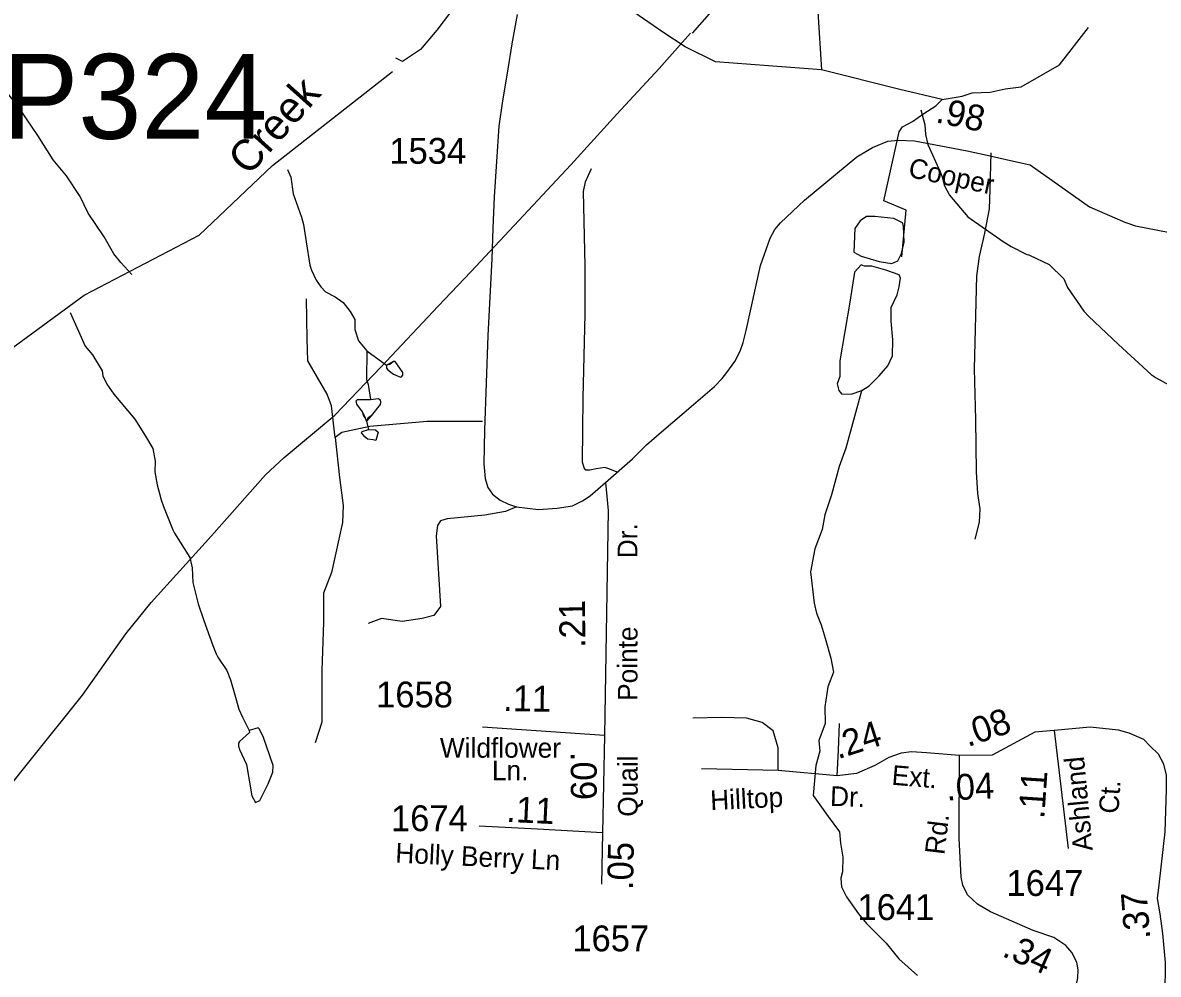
# Model space of a CAD drawing. Extents: x 1473865 to 1648260, y 639067 to 773536.
# Drawn here: x 1520569 to 1526062, y 681743 to 686345 of the extents above; entities that cross this region are included whole.
import ezdxf

# ---------------------------------------------------------------- set-up
doc = ezdxf.new("R2010")
doc.units = 0
for name, color, linetype in [('Exist Hydrographic Creek Single Shore', 7, 'Continuous'), ('Exist Hydrographic Creek Single Shore Label', 7, 'Continuous'), ('Exist Hydrographic Misc Water Feature', 7, 'Continuous'), ('Exist Hydrographic Pond Over 1500 Sq Ft', 7, 'Continuous'), ('Exist Hydrographic Pond Under 1500 Sq Ft', 7, 'Continuous'), ('Exist Road Non-System Type 51', 7, 'Continuous'), ('Exist Road Secondary Mileage Hundredths English Label', 7, 'Continuous'), ('Exist Road Secondary Structure Pipe Number Label', 7, 'Continuous'), ('Exist Road Secondary Type 51 Attributed', 7, 'Continuous'), ('Exist Road Secondary Type 51 Label', 7, 'Continuous'), ('Exist Road Secondary Type 51 Number Label', 7, 'Continuous'), ('Exist Utilities Electrical Transmission Line', 7, 'Continuous')]:
    doc.layers.add(name, color=color, linetype=linetype)

msp = doc.modelspace()

# ---------------------------------------------------------------- linework, layer by layer
at = {"layer": 'Exist Hydrographic Creek Single Shore'}
for points in [[(1523666, 686298.8), (1523432.2, 686461.6), (1523382.8, 686513), (1523294.5, 686557.7), (1523201.6, 686564.8), (1522986.7, 686628.2), (1522734, 686471.2), (1522659.1, 686431.8), (1522639.1, 686396.5), (1522572, 686309.4), (1522493.2, 686215.3), (1522406.1, 686157.7), (1522373.2, 686173.5)], [(1525016, 685972.9), (1525113.7, 685989.4), (1525161.9, 686005.9), (1525249, 686009.4), (1525320.8, 686024.7), (1525398.4, 686035.3), (1525584.4, 686140.6), (1525724.7, 686321.8)], [(1525016, 685972.9), (1524812.4, 686022.3), (1524432.3, 686116.3), (1523920.5, 686155.3), (1523773.5, 686227.8), (1523666, 686298.8)], [(1517072, 680044.5), (1517310.1, 680437), (1517438.1, 680611.7), (1517759.1, 680897.3), (1518003.1, 681043.4), (1518182.1, 681266.3), (1518591.3, 682427), (1519143.1, 682993.2), (1519774.2, 683899.6), (1519995.1, 684206.9), (1520521.2, 684774.1), (1520867.2, 685026.4), (1521422.2, 685317.2), (1521777.2, 685654.6), (1522357.9, 686108.2)], [(1524630.1, 684570), (1524623.9, 684558.7), (1524550, 684287.9), (1524518.3, 684198.5), (1524480.6, 684062), (1524449, 683964.4), (1524435.9, 683894.1), (1524400.6, 683800.8), (1524379.7, 683689.3), (1524397.5, 683537.1), (1524408.8, 683488.4), (1524431.8, 683432.2), (1524450.8, 683367.8), (1524477.5, 683271.2), (1524490.2, 683203.7)], [(1524490.2, 683203.7), (1524463, 683132.4), (1524449.5, 683035.5), (1524450.3, 682955.1), (1524420.6, 682873.5), (1524424.1, 682821.8), (1524405.3, 682752.3), (1524392.4, 682607.6), (1524465.3, 682505.2), (1524519.4, 682432.3), (1524525.2, 682376.6), (1524536.2, 682309.9), (1524535.2, 682238.5), (1524526.6, 682208.3), (1524529.9, 682166.5), (1524553.2, 682117.5), (1524611.9, 682035.1), (1524651.1, 681988.4), (1524745.9, 681892.9), (1524806.7, 681817.8), (1524897.3, 681736.4)]]:
    msp.add_lwpolyline(points, dxfattribs=at)
at = {"layer": 'Exist Hydrographic Misc Water Feature'}
for p, q in [((1522233.7, 684757.5), (1522328.7, 684688.3)), ((1522232.3, 684417), (1522241.9, 684377.4))]:
    msp.add_line(p, q, dxfattribs=at)
for points in [[(1524415.1, 686396.7), (1524432.3, 686116.3)], [(1521097.3, 685127.6), (1521044.1, 685184.5), (1521010.6, 685227), (1520963.9, 685310), (1520885.8, 685423.2), (1520847, 685503.6), (1520780.5, 685605), (1520715.8, 685681.8), (1520641.6, 685799), (1520549.6, 685934.6), (1520486.8, 686015.5), (1520398.1, 686096.9), (1520323.1, 686159.9), (1520251.9, 686221.3), (1520207.1, 686290.3), (1520168.2, 686352.6)], [(1524734.3, 685483.4), (1524808.9, 685816.4), (1524825.4, 685841.1), (1524872.4, 685867), (1524927.7, 685905.8), (1524986.6, 685942.3), (1525016, 685972.9)], [(1524913.4, 685923.7), (1524932.3, 685851.1), (1524935.3, 685803.5), (1524946.7, 685755.6), (1525006.6, 685623.9), (1525016.2, 685599.9), (1525027.6, 685556.2), (1525052.7, 685511.4), (1525141.3, 685406.2), (1525311.4, 685287.1), (1525351, 685262.5), (1525422.4, 685225.8), (1525438.5, 685221.3), (1525533.9, 685175.9), (1525604.6, 685106.4), (1525622.1, 685064.2), (1525702.2, 684949.3), (1525723.9, 684925.1), (1525869.9, 684788.3), (1526027.5, 684644), (1526051.2, 684627.1), (1526116.8, 684592.2)], [(1521849.5, 685634.3), (1521866.8, 685597.8), (1521877.5, 685517.2), (1521917.9, 685404.8), (1521927.2, 685368.5), (1521939.9, 685284.6), (1521958.2, 685171.7), (1521965.9, 685147.8), (1521989.1, 685099.7), (1522010.6, 685067.3), (1522034.4, 685043), (1522079.8, 685018.3), (1522119.5, 684991.2), (1522152.9, 684948.7), (1522176.3, 684908.9), (1522175.4, 684860.5), (1522192.7, 684805.9), (1522233.7, 684757.5)], [(1520798.1, 684944), (1520871.5, 684780.9), (1520907, 684738.4), (1520953.6, 684661.9), (1520957.5, 684637.2), (1520976.8, 684597.4), (1521010, 684548.3), (1521112.2, 684427.3), (1521162.9, 684345.8), (1521198, 684285.3), (1521209.1, 684225.1), (1521208.2, 684173.4), (1521219.3, 684109.2), (1521238.1, 684036.6), (1521249.5, 684004.3), (1521295.7, 683891.8), (1521303.6, 683876.1), (1521377.8, 683758.9), (1521388.9, 683708.6), (1521391.9, 683638), (1521418.2, 683534), (1521445, 683453), (1521489.1, 683332.3), (1521504.4, 683292.6), (1521512.2, 683276.1), (1521557.1, 683211.2), (1521574.4, 683167.3), (1521595.3, 683094.7), (1521614.2, 683024.5), (1521631.7, 682986.5), (1521664.6, 682921.8)], [(1522233.7, 684757.5), (1522231.7, 684619.7), (1522239.3, 684595.8), (1522252.1, 684523.3)], [(1522328.7, 684688.3), (1522328.4, 684674.4), (1522334.5, 684666), (1522362.1, 684645.8), (1522395.9, 684631.2), (1522401.9, 684632.7), (1522408, 684640.8), (1522408.3, 684653.1), (1522371.2, 684707.1), (1522363.2, 684705.7), (1522344.8, 684692.1), (1522328.7, 684688.3)], [(1522328.7, 684688.3), (1522328.4, 684674.4), (1522334.5, 684666), (1522362.1, 684645.8), (1522395.9, 684631.2), (1522401.9, 684632.7), (1522408, 684640.8), (1522408.3, 684653.1), (1522371.2, 684707.1), (1522363.2, 684705.7), (1522328.7, 684688.3)], [(1522232.3, 684417), (1522226.7, 684431.9), (1522218.9, 684441.9), (1522213.2, 684463.3), (1522185.8, 684500), (1522182.1, 684516.5), (1522188.1, 684522.1), (1522252.1, 684523.3)], [(1522232.3, 684417), (1522226.7, 684431.9), (1522213.2, 684463.3), (1522185.8, 684500), (1522182.1, 684516.5), (1522188.1, 684522.1), (1522252.1, 684523.3)], [(1522252.1, 684523.3), (1522290.2, 684526.6), (1522298.1, 684520.7), (1522299.9, 684510), (1522297.8, 684498.6), (1522254.9, 684442.8), (1522238.6, 684431.7), (1522232.3, 684417)], [(1522252.1, 684523.3), (1522290.2, 684526.6), (1522298.1, 684520.7), (1522299.9, 684510), (1522297.8, 684498.6), (1522254.9, 684442.8), (1522232.3, 684417)], [(1522241.9, 684377.4), (1522275.8, 684375.1), (1522287.7, 684364.2), (1522277, 684325), (1522265, 684326.9), (1522237.1, 684331.5), (1522223.2, 684341.7), (1522207.6, 684361.7), (1522211.6, 684367.4), (1522241.9, 684377.4)], [(1521664.6, 682921.8), (1521666.5, 682911.9), (1521617.9, 682868.5), (1521613.6, 682860.4), (1521613.5, 682846.5), (1521617.1, 682830), (1521652.1, 682757.9), (1521677.6, 682605.6), (1521695.2, 682573.2), (1521715.3, 682582.7), (1521756.7, 682663.9), (1521779.6, 682720), (1521780, 682752), (1521764.8, 682800), (1521734.2, 682888.4), (1521714.9, 682929), (1521708.8, 682934.8), (1521664.6, 682921.8)]]:
    msp.add_lwpolyline(points, dxfattribs=at)
at = {"layer": 'Exist Hydrographic Pond Over 1500 Sq Ft'}
for points in [[(1524620.6, 685386.9), (1524594.7, 685349.3), (1524588.9, 685235.1), (1524624.2, 685216.3), (1524711.2, 685190.4), (1524772.4, 685181), (1524801.8, 685192.8), (1524819.5, 685229.3), (1524832.4, 685283.4), (1524828.9, 685361), (1524825.4, 685377.5), (1524783, 685397.5), (1524690.1, 685408.1), (1524651.2, 685406.9)], [(1524624.2, 685174), (1524592.4, 685138.7), (1524570, 684993.9), (1524521.8, 684709.2), (1524521.8, 684633.9), (1524508.8, 684598.6), (1524517.1, 684566.8), (1524530, 684550.3), (1524575.9, 684549.1), (1524627.7, 684565.6), (1524663, 684588), (1524711.2, 684636.2), (1524753.6, 684685.6), (1524776, 684733.9), (1524777.1, 684811.5), (1524770.1, 684902.1), (1524770.1, 684966.9), (1524798.3, 685028), (1524808.9, 685066.9), (1524814.8, 685109.2), (1524808.9, 685125.7), (1524744.2, 685148.1), (1524677.1, 685166.9), (1524640.6, 685166.9)]]:
    msp.add_lwpolyline(points, close=True, dxfattribs=at)
at = {"layer": 'Exist Hydrographic Pond Under 1500 Sq Ft'}
msp.add_lwpolyline([(1524821.2, 685212.5), (1524842.2, 685438.6), (1524734.3, 685483.4)], dxfattribs=at)
at = {"layer": 'Exist Road Non-System Type 51'}
for points in [[(1525176.3, 683846.3), (1525197.8, 683929.9), (1525201.1, 683993.6), (1525188.6, 684067.9), (1525182.5, 684172.1), (1525179.4, 684426.1), (1525172.1, 684670.2), (1525184.6, 685119.9), (1525196.5, 685213.7), (1525222.6, 685327.3), (1525245, 685444.9), (1525248.7, 685538.9), (1525253.7, 685714.8)], [(1523443.9, 684171.7), (1523409.8, 684185.7), (1523385, 684193.4), (1523343.1, 684187.2), (1523312, 684181), (1523293.4, 684181), (1523284.1, 684191.9), (1523276.4, 684219.8), (1523279.5, 684530.2), (1523289.6, 684934.6), (1523290.3, 685168.2), (1523281.8, 685529.1), (1523291.1, 685575.7), (1523319.8, 685640.1)], [(1522080.3, 684338.4), (1522062.5, 684491.9), (1522041.1, 684549), (1521948.4, 684709.6), (1521944.8, 684816.7), (1521941.2, 685009.4)], [(1522793.5, 684416.9), (1522526.1, 684416.9), (1522247.9, 684391.9), (1522112.4, 684363.4), (1522080.3, 684338.4)], [(1522080.3, 684338.4), (1522101.7, 684145.6), (1522119.5, 684010), (1522116, 683927.9), (1522062.5, 683685.2), (1522023.3, 683585.2), (1522023.3, 683446), (1522016.2, 683212.6), (1522016.2, 683034.2), (1522016.2, 682962.8), (1521984.1, 682862.8)], [(1522957.6, 684002.9), (1522904.1, 683981.4), (1522804.2, 683963.6), (1522622.4, 683945.7), (1522590.3, 683935), (1522576, 683913.6), (1522568.9, 683863.6), (1522590.3, 683521), (1522558.2, 683478.2), (1522501.1, 683463.9), (1522404.8, 683449.6), (1522305, 683463.9), (1522240.8, 683438.9)], [(1524222.8, 682727.9), (1524222.8, 682837.3), (1524198.3, 682920.3), (1524145.4, 682960), (1524070.5, 682980.6), (1523951.5, 682985), (1523810.4, 682982.1)], [(1524508.2, 682702.9), (1524515.7, 682827.2), (1524520.6, 682956.4)]]:
    msp.add_lwpolyline(points, dxfattribs=at)
at = {"layer": 'Exist Road Secondary Type 51 Attributed'}
msp.add_line((1525558.4, 682921.4), (1525625.9, 682350.7), dxfattribs=at)
for points in [[(1522961.5, 686384.8), (1522935.6, 686242.4), (1522913.3, 686110.6), (1522889.7, 685967), (1522872.1, 685844.7), (1522849.7, 685503.4), (1522843.8, 685351.6), (1522838, 685202.2), (1522819, 684831.8), (1522802.7, 684373.8), (1522799.1, 684211.4), (1522806.2, 684139.7), (1522819.1, 684097.3), (1522841.5, 684065.5), (1522879.1, 684035), (1522919.2, 684016.1), (1522957.6, 684002.9), (1523063.9, 683990.2), (1523154.5, 683997.3), (1523228.6, 684009), (1523276.9, 684032.6), (1523313.3, 684056.1), (1523387.5, 684120.8)], [(1523387.5, 684120.8), (1523519.3, 684236.1), (1523586.7, 684303.9), (1523659.3, 684365.6), (1523768.7, 684459.7), (1523914.6, 684585.6), (1523952.3, 684623.3), (1523974.6, 684652.9), (1524013.5, 684706.8), (1524039.4, 684756.2), (1524053.5, 684797.4), (1524068.8, 684856.2), (1524138.4, 685170.4), (1524184.1, 685303.4), (1524206.4, 685344.6), (1524234.7, 685377.5), (1524351.2, 685486.9), (1524604.2, 685696.4), (1524679.5, 685741.1), (1524753.6, 685771.7), (1524803, 685776.4), (1524883, 685774.1), (1525137.2, 685724.6), (1525233.7, 685704.6), (1525346.6, 685678.7), (1525441.7, 685657.7), (1525728.6, 685453.7), (1525900.2, 685380.7), (1525952.4, 685362.8), (1526333.1, 685287.5)], [(1523387.5, 684120.8), (1523401.6, 683985.5), (1523383.9, 682897.1)], [(1523383.9, 682897.1), (1522792.9, 682938.1)], [(1525558.4, 682921.4), (1525465.4, 682913), (1525258.4, 682803.1), (1525101, 682801.3)], [(1525953.8, 681077.9), (1526040.9, 681294.4), (1526079.7, 681429.8), (1526092.7, 681534.5), (1526095, 681645.1), (1526097.4, 681799.2), (1526083.2, 681939.3), (1526071.5, 682034.6), (1526058.5, 682108.7), (1526065.6, 682175.8), (1526095, 682432.3), (1526100.9, 682637), (1526100.9, 682706.5), (1526087.9, 682758.2), (1526062.1, 682807.7), (1526023.2, 682846.5), (1525991.5, 682878.3), (1525921.7, 682908.8), (1525870.2, 682922.6), (1525731.6, 682938.3), (1525558.4, 682921.4)], [(1523383.9, 682897.1), (1523373.6, 682426.9)], [(1525101, 682801.3), (1524940.5, 682814), (1524868.7, 682818.2), (1524818, 682811.9), (1524758.8, 682790.7), (1524691.2, 682752.7), (1524602.5, 682714.6), (1524508.2, 682702.9), (1524222.8, 682727.9), (1523852.7, 682735.8)], [(1525528.2, 681173.3), (1525620.5, 681502.2), (1525666.7, 681694.4), (1525672.6, 681726), (1525674.5, 681764.8), (1525667.9, 681801.6), (1525644.3, 681847.5), (1525614.9, 681881.6), (1525556.1, 681920.4), (1525455.9, 681954.8), (1525250.2, 682045.2), (1525186.6, 682081.6), (1525138.4, 682126.4), (1525117.2, 682173.4), (1525109, 682212.3), (1525099.5, 682400.5), (1525101, 682801.3)], [(1523373.6, 682426.9), (1523058.4, 682445.1), (1522777, 682458.3)], [(1523373.6, 682426.9), (1523368.9, 682177.9)]]:
    msp.add_lwpolyline(points, dxfattribs=at)
at = {"layer": 'Exist Utilities Electrical Transmission Line'}
for points in [[(1526240.6, 689003.8), (1526008, 688741.5), (1525759.2, 688463.6), (1525478, 688150.3), (1525196.9, 687845), (1524970.3, 687582.7), (1524686.9, 687265.4), (1524466.8, 687019.1), (1524226.2, 686747.1), (1524006.3, 686520.8), (1523806.5, 686293.9)], [(1520286.1, 682378.8), (1520605.1, 682776.9), (1520858.8, 683092.4), (1521067.9, 683388.5), (1521190.6, 683540.3), (1521482.2, 683863.2), (1521743.5, 684158.3), (1521833.1, 684242.7), (1522078.5, 684446.2), (1522302.7, 684680.2), (1522578, 684973.2), (1522736.8, 685140.3), (1522969.1, 685388.1), (1523219.9, 685657.6), (1523442.3, 685901.7), (1523648.1, 686123.8), (1523799.2, 686293.9)]]:
    msp.add_lwpolyline(points, dxfattribs=at)

# ---------------------------------------------------------------- texts
at = {"layer": 'Exist Hydrographic Creek Single Shore Label'}
msp.add_text('Creek', height=150, rotation=48.1908, dxfattribs=at).set_placement((1521661.8, 685599.5))
at = {"layer": 'Exist Road Secondary Mileage Hundredths English Label'}
for s, rotation, p in [('.98', 347.9733, (1524980.6, 685864.1)), ('.21', 90.803, (1523291.4, 683321.5)), ('.11', 359.0127, (1522892.2, 683016.2)), ('.08', 18.773, (1525140.2, 682841.2)), ('.24', 17.9873, (1524512.5, 682782)), ('.09', 270.094, (1523220.2, 682818.1)), ('.04', 2.8213, (1525038.8, 682582.6)), ('.11', 86.1339, (1525510.1, 682492.1)), ('.11', 357.3204, (1522906.5, 682480)), ('.05', 88.9299, (1523521.2, 682149.2)), ('.37', 94.5461, (1526023.4, 681914.7)), ('.34', 336.2487, (1525301.3, 681832.5))]:
    msp.add_text(s, height=125, rotation=rotation, dxfattribs=at).set_placement(p)
at = {"layer": 'Exist Road Secondary Structure Pipe Number Label'}
msp.add_text('P324', height=410.1, dxfattribs=at).set_placement((1520472.2, 685783.2))
at = {"layer": 'Exist Road Secondary Type 51 Label'}
for s, rotation, p in [('Cooper', 347.9733, (1524848, 685600)), ('Dr.', 90, (1523541.9, 683754.7)), ('Pointe', 90, (1523542.8, 683064.9)), ('Quail', 90, (1523543.7, 682504.5)), ('Ext.', 355.2485, (1524769.8, 682659.8)), ('Ashland', 95.3638, (1525744.9, 682342.7)), ('Hilltop', 2.8213, (1523896.9, 682536.1)), ('Dr.', 357.888, (1524472.9, 682557.6)), ('Ct.', 86.1339, (1525868.9, 682517.2)), ('Rd.', 83.1127, (1525026.8, 682317.8)), ('Holly Berry Ln', 357.3204, (1522370, 682283.1))]:
    msp.add_text(s, height=95, rotation=rotation, dxfattribs=at).set_placement(p)
for s, p in [('Wildflower', (1522587.1, 682790.2)), ('Ln.', (1522838.8, 682681.4))]:
    msp.add_text(s, height=95, dxfattribs=at).set_placement(p)
at = {"layer": 'Exist Road Secondary Type 51 Number Label'}
for s, p in [('1534', (1522342.5, 685662.4)), ('1658', (1522278.5, 683033.5)), ('1674', (1522350.3, 682434.9)), ('1647', (1525327.4, 682121.6)), ('1641', (1524606.9, 682005.1)), ('1657', (1523227.5, 681853.8))]:
    msp.add_text(s, height=125, dxfattribs=at).set_placement(p)

doc.saveas('drawing.dxf')
